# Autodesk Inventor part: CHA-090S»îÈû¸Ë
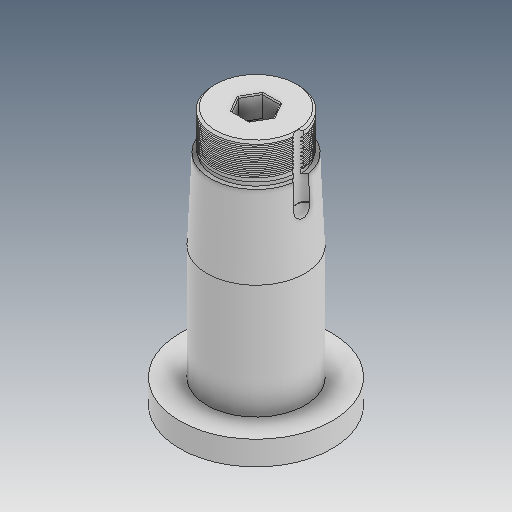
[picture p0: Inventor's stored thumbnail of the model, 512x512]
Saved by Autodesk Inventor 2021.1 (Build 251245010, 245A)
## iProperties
Created: 2019-05
Part Number: CHA-090S»îÈû¸Ë
Material: Ogólny
Document SubType Name: Modeling
Designer: user
Density: 1 g/cm^3
Appearance: Domyślna
Author: user
Revision Number: ÈÎºÎ
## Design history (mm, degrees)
feature "ÊäÈë1"
node "Bryła1"
